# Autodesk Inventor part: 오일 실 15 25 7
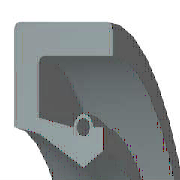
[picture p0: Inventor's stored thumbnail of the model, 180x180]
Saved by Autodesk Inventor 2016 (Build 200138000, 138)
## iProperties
Created: 2012-02
Part Number: 오일 실 15 25 7
Material: 고무
Description: 오일-실
Document SubType Name: Modeling
Standard: KS B 2804
Designer: mduedu
Standards Organization: KS
Language: ko-KR
Size Designation: S - 15 25 7
Categories: <MemberInstance><Categories><Category DisplayName="샤프트 부품" InternalName="7f7aeb1f-a693-4053-b835-cee3144e0d98" Mnemonic="SHFT"><Category DisplayName="실링" Intern
Density: 0.93 g/cm^3
Appearance: 고무 - 검은색 - 버전 1.1
IsCustomPart: 1
Author: mduedu
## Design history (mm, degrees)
revolve "본체" stored, may be unused: angle "d17" = 90 deg
revolve "스프링1" stored, may be unused: angle "d18" = 90 deg
body "Solid1"
sketch "스케치1"
  geometry: L1 (0, 12.5)-(7, 12.5); L2 (7, 12.5)-(7, 11.25); L3 (7, 11.25)-(1.75, 11.25); L4 (0, 12.5)-(0, 9.6); L5 (0, 9.6)-(1.75, 9.25); L6 (1.75, 9.25)-(4.9, 7.5); L7 (4.9, 7.5)-(0, 7.5); L8 (6.3, 8.375)-(6.3, 9.6); L9 (0, 0)-(9.586, 0) reference; L10 (4.9, 7.5)-(6.3, 8.375); L11 (0, 18)-(0, -3) reference; L12 (-1.917, 0)-(11.503, 0) reference; L13 (4.2, 9.6)-(1.75, 10.09); L14 (1.75, 10.09)-(1.75, 11.25); L15 (6.3, 9.6)-(5.6, 9.6); C1 r 0.455 at (4.9, 9.6); A1 r 0.7 centre (4.9, 9.6) between (5.6, 9.6) and (4.2, 9.6)
  constraints: 26 end point, 5 horizontal alignment, 4 perpendicular, 2 centre point, 2 collinear, 2 horizontal, 2 parallel, 2 point on circle, 2 point on line, 2 vertical alignment, 1 coincident
  dimensions: "d0" = 25 diameter of L1 L9 (= SD2); "d1" = 16.75 diameter of L8.start L9 (= ABDM); "d2" = 1.25 distance of L1.end L2.end (computed from SD); "d3" = 0.91 diameter of C1 (= SPDI); "d4" = 1.4 diameter of A1 (= SPDA); "d5" = 15 diameter of L6.end L9 (= NND); "d6" = 18.5 diameter of L5.end L9 (= TKDM); "d7" = 19.2 diameter of L4.end L9 (= HLDM); "d8" = 4.9 distance from line of C1.centre L4 (= SPDST); "d9" = 6.3 distance between parallel lines of L8 L4 (= SDI); "d10" = 7 distance between parallel lines of L2 L4 (= SWDT); "d12" = 1.75 distance between parallel lines of L14 L4 (= SD)
fillet "모깎기1" dims "d11" = 0.3 (= RR)
other parameters: "SD2" = 25 [user parameter; used in 1 equation term], "SWDT" = 7 [user parameter; used in 1 equation term], "RR" = 0.3 [user parameter; used in 1 equation term], "SD" = 1.75 [user parameter; used in 2 equation terms], "NND" = 15 [user parameter; used in 1 equation term], "SPDA" = 1.4 [user parameter; used in 1 equation term], "SPDI" = 0.91 [user parameter; used in 1 equation term], "TKDM" = 18.5 [user parameter; used in 1 equation term], "HLDM" = 19.2 [user parameter; used in 1 equation term], "ABDM" = 16.75 [user parameter; used in 1 equation term], "SDI" = 6.3 [user parameter; used in 1 equation term], "SPDST" = 4.9 [user parameter; used in 1 equation term], "d13" = 0, "d14" = 0, "d15" = 0, "LAB" = 0.35 [user parameter]
